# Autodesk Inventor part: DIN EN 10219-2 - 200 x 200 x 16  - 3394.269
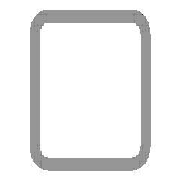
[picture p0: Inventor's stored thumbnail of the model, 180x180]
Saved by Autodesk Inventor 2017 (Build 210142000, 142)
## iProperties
IsCustomPart: 1
_CCFamilyMember: 103
_CCFamilyDisplayName: DIN EN 10219-2 (Square Hollow Section - Cold Formed) - Cold formed welded structural hollow sections of non-alloy and fine grain structural steel
_FrameMemberDoc: Frame Member File
_Version: 15.0.0
_GetPNFromCC: 1
Created: 2017-11
Part Number: DIN EN 10219-2 - 200 x 200 x 16  - 3394.269
Material: Steel, Mild
Description: Cold formed welded structural hollow sections of non-alloy and fine grain structural steel
Document SubType Name: Modeling
Standard: DIN
Designer: iusti
Standard Revision: 2006-07
Standards Organization: DIN
Language: en-US
Size Designation: 200 x 200 x 16
Categories: <MemberInstance><Categories><Category DisplayName="Structural Shapes" InternalName="089c4875-fa83-4c05-b084-43b9cc11f5ed" Mnemonic="GRDR"><CategoryParameter Dis
Stock Number: 200 x 200 x 16
Density: 7.85 g/cm^3
Appearance: Semi-Polished
Mass: 259456 g
Surface Area: 41726.7 cm^2
Volume: 33051.7 cm^3
G_L: 3394.269 mm
G_W: 200.000 mm
G_H: 200.000 mm
+4654C135-6D8C-4950-BBE2-01DB03A734B6+CUTDETAIL1: Cut
+D2B28E9A-99E0-4240-A9A6-2079430655EE+CUTDETAIL2: Cut
Author: iusti
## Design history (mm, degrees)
node "Start plane"
node "End plane"
sketch "Sketch"
  geometry: L1 (-100, -52)-(-100, 52); L2 (-52, 100)-(52, 100); L3 (100, 52)-(100, -52); L4 (52, -100)-(-52, -100); L5 (-52, 84)-(52, 84); L6 (84, 52)-(84, -52); L7 (52, -84)-(-52, -84); L8 (-84, -52)-(-84, 52); L9 (0, 153.918)-(0, -153.918) reference; L10 (-153.918, 0)-(153.918, 0) reference; A1 r 48 centre (-52, -52) between (-100, -52) and (-52, -100); A2 r 48 centre (-52, 52) between (-52, 100) and (-100, 52); A3 r 48 centre (52, 52) between (100, 52) and (52, 100); A4 r 48 centre (52, -52) between (52, -100) and (100, -52); A5 r 32 centre (-52, 52) between (-52, 84) and (-84, 52); A6 r 32 centre (52, 52) between (84, 52) and (52, 84); A7 r 32 centre (52, -52) between (52, -84) and (84, -52); A8 r 32 centre (-52, -52) between (-84, -52) and (-52, -84)
  constraints: 16 end point, 16 point on circle, 8 centre point, 8 tangent, 4 parallel, 3 equal radius, 2 perpendicular, 7 other
  dimensions: "d7" = 48 radius of A1 (= G_IR); "d10" = 200 distance between parallel lines of L2 L4 (= G_H); "d11" = 200 distance between parallel lines of L1 L3 (= G_W); "d12" = 16 distance between parallel lines of L3 L6 (= G_T); "d15" = 100 distance between parallel lines of L2 L10 (= 0.5 x d10); "d16" = 100 distance between parallel lines of L9 L3 (= 0.5 x d11)
extrude "Body" new body sketch "Sketch" stored distance "d3" = 3394.26947 (= G_L); taper "d4" = 0 deg
node "Driven Length"
  sketch "Sketch3"
    geometry: L1 (0, 0)-(10, 0) reference
    constraints: 2 end point, 1 horizontal
  workplane "Work Plane3"
  sketch "Sketch4"
    geometry: L1 (-2, 73.146)-(12, 73.146) reference; L2 (-2, 3467.416)-(12, 3467.416) reference
    dimensions: "d18" = 3394.26947 distance between parallel lines of L1 L2 (derived)
workplane "Work Plane4"
split "Split1"
workplane "Work Plane5"
split "Split2"
body "Solid1"
other parameters: "G_W" = 200 [user parameter; used in 1 equation term], "G_H" = 200 [user parameter; used in 1 equation term], "G_T" = 16 [user parameter; used in 1 equation term], "G_IR" = 48 [user parameter; used in 1 equation term], "G_L" = 3394.26947 (= d18) [user parameter; used in 1 equation term], "G_OFFSET_START" = -73.14647 [user parameter; used in 1 equation term], "G_OFFSET_END" = -18.54571 [user parameter; used in 1 equation term], "d13" = 73.14647 (= -G_OFFSET_START), "d14" = 3467.41594 (= G_OFFSET_END + B_L), "B_L" = 3485.96166 [user parameter; used in 1 equation term], "d17" = 90 deg
